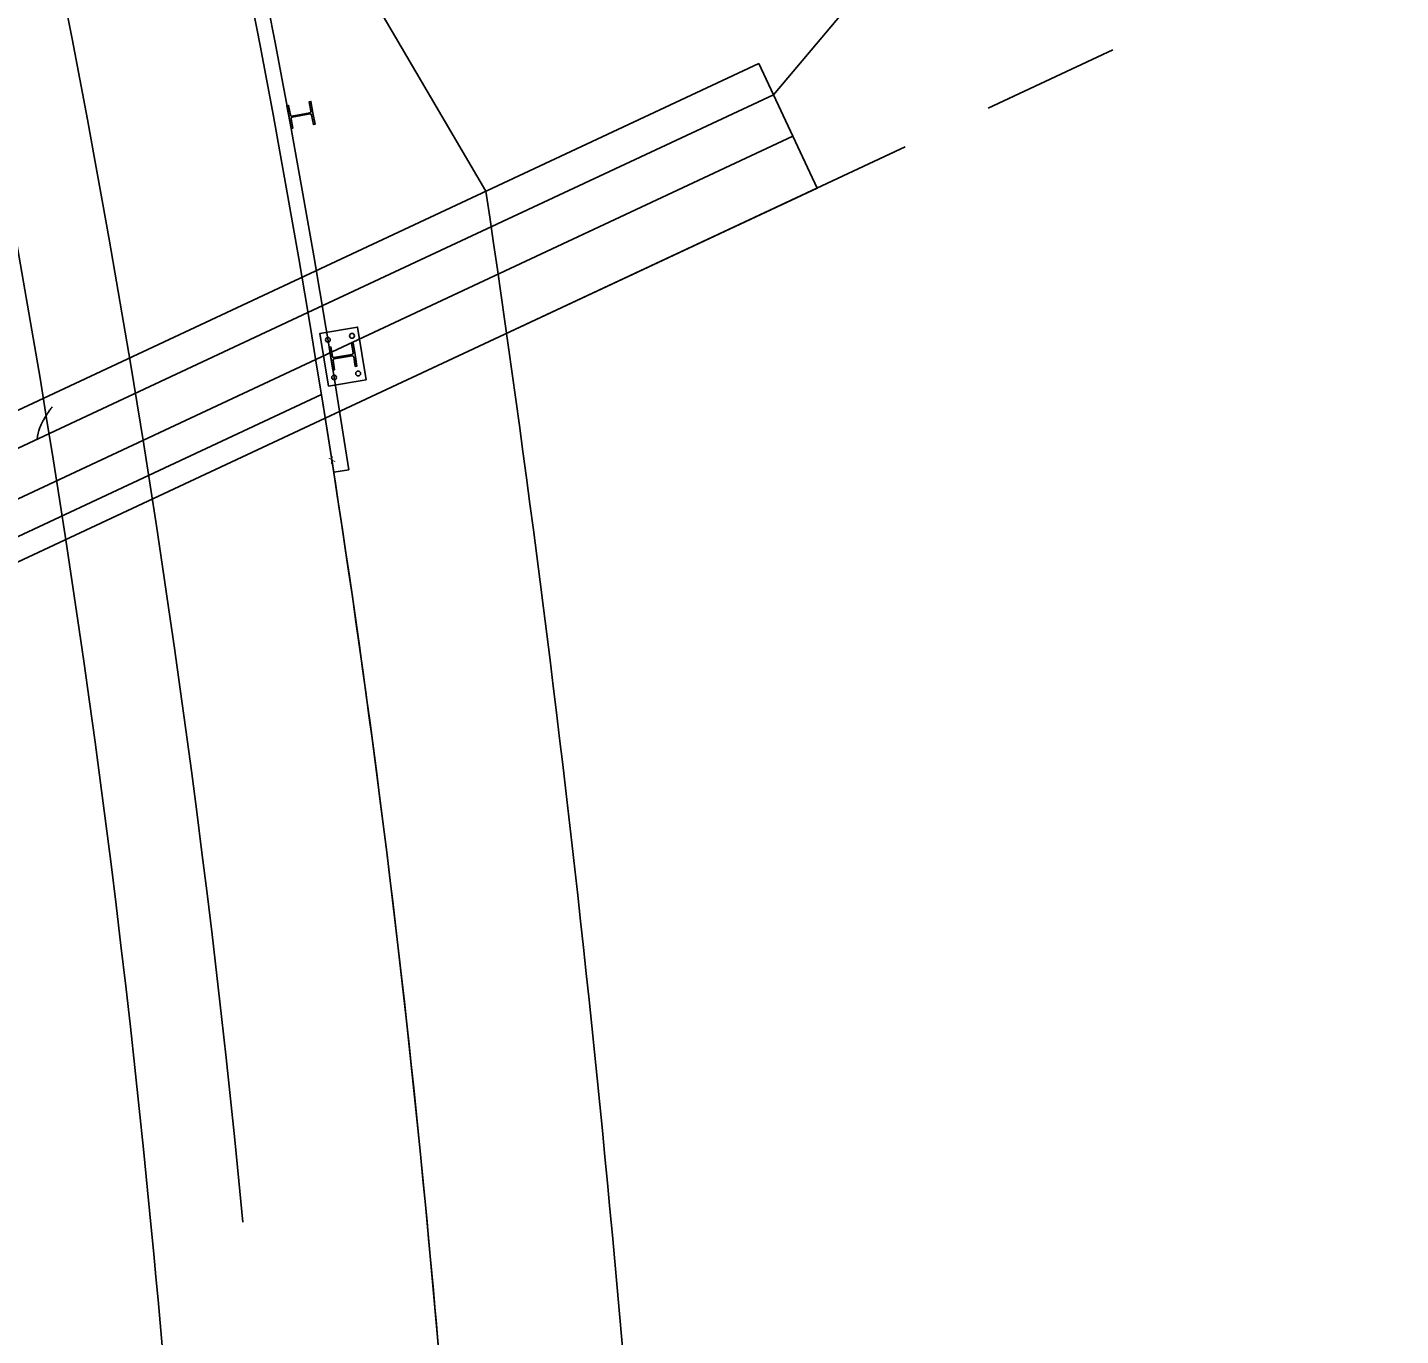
# Model space of a CAD drawing. Extents: x 2355002 to 2355569, y 708374 to 709566.
# Drawn here: x 2355370.84 to 2355400.79, y 709251.3 to 709279.85 of the extents above; entities that cross this region are included whole.
import ezdxf

# ---------------------------------------------------------------- set-up
doc = ezdxf.new("R2010")
doc.units = 0
for name, color, linetype in [('BD_X_Building', 7, 'Continuous'), ('BR_X_Brg_Centerline', 7, 'Continuous'), ('BR_X_Gen_Approach_Slab', 7, 'Continuous'), ('BR_X_Rail_Stl_Det', 7, 'Continuous'), ('DR_X_Cells', 7, 'Continuous'), ('DT_X_Slope_Break_Line', 7, 'Continuous'), ('GK_Drainage_Nodes', 7, 'Continuous'), ('PM_X_Edge_Line', 7, 'Continuous'), ('PM_X_Stop_Line', 7, 'Continuous'), ('PV_X_Driveway', 7, 'Continuous'), ('RD_X_GR_Lt', 7, 'Continuous'), ('VG_X_Cells', 7, 'Continuous'), ('VG_X_Tree_Line_Rt', 7, 'Continuous')]:
    doc.layers.add(name, color=color, linetype=linetype)

msp = doc.modelspace()

# ---------------------------------------------------------------- linework, layer by layer
at = {"layer": 'BD_X_Building'}
msp.add_arc((2355104.75, 709227.886), 272.024, 5.4603, 29.69206, dxfattribs=at)
at = {"layer": 'BR_X_Brg_Centerline'}
msp.add_line((2355335.913, 709253.31), (2355387.539, 709277.472), dxfattribs=at)
at = {"layer": 'BR_X_Gen_Approach_Slab'}
msp.add_line((2355343.137, 709255.863), (2355377.253, 709271.831), dxfattribs=at)
for centre, radius, start, end in [((2355104.75, 709227.886), 276.024, 5.45948, 9.16072), ((2354973.054, 709215.293), 408.32, 3.78138, 5.4603)]:
    msp.add_arc(centre, radius, start, end, dxfattribs=at)
at = {"layer": 'BR_X_Rail_Stl_Det'}
msp.add_line((2355377.85, 709270.19), (2355377.521, 709270.139), dxfattribs=at)
for points in [[(2355376.591, 709277.851), (2355376.629, 709277.644), (2355376.592, 709277.638), (2355376.5, 709278.136), (2355376.537, 709278.143), (2355376.575, 709277.936)], [(2355377.024, 709278.018), (2355376.986, 709278.225), (2355377.023, 709278.232), (2355377.069, 709277.983)], [(2355376.61, 709277.912), (2355377, 709277.984)], [(2355377.005, 709277.958), (2355376.615, 709277.886)], [(2355377.069, 709277.983), (2355377.115, 709277.734), (2355377.077, 709277.727), (2355377.039, 709277.934)], [(2355378.231, 709272.153), (2355378.042, 709273.304), (2355377.219, 709273.169), (2355377.408, 709272.018), (2355378.231, 709272.153)], [(2355377.507, 709272.581), (2355377.541, 709272.374), (2355377.504, 709272.368), (2355377.422, 709272.868), (2355377.459, 709272.874), (2355377.493, 709272.667)], [(2355377.943, 709272.74), (2355377.909, 709272.948), (2355377.946, 709272.954), (2355377.987, 709272.704)], [(2355377.527, 709272.642), (2355377.918, 709272.706)], [(2355377.923, 709272.68), (2355377.532, 709272.616)], [(2355377.987, 709272.704), (2355378.028, 709272.454), (2355377.991, 709272.448), (2355377.957, 709272.655)]]:
    msp.add_lwpolyline(points, dxfattribs=at)
for centre in [(2355377.395, 709273.029), (2355377.92, 709273.115), (2355377.53, 709272.207), (2355378.055, 709272.293)]:
    msp.add_circle(centre, 0.0521, dxfattribs=at)
for centre, radius, start, end in [((2355104.75, 709227.887), 276.357, 8.80517, 29.69195), ((2355104.75, 709227.887), 276.024, 8.80517, 29.69195), ((2355104.75, 709227.887), 276.024, 8.80517, 29.69195), ((2355376.605, 709277.941), 0.0298, 190.4236, 280.4236), ((2355376.62, 709277.857), 0.0298, 100.4236, 190.4236), ((2355376.994, 709278.013), 0.0298, 280.4236, 10.4236), ((2355377.01, 709277.928), 0.0298, 10.4236, 100.4236), ((2355377.522, 709272.671), 0.0298, 189.3148, 279.3148), ((2355377.536, 709272.586), 0.0298, 99.3148, 189.3148), ((2355377.913, 709272.736), 0.0298, 279.3148, 9.3148), ((2355377.927, 709272.65), 0.0298, 9.3148, 99.3148)]:
    msp.add_arc(centre, radius, start, end, dxfattribs=at)
at = {"layer": 'DR_X_Cells'}
for p, q in [((2355376.958, 709273.624), (2355387.115, 709278.378)), ((2355387.115, 709278.378), (2355388.069, 709276.34)), ((2355377.336, 709271.317), (2355388.069, 709276.34))]:
    msp.add_line(p, q, dxfattribs=at)
at = {"layer": 'DT_X_Slope_Break_Line'}
for p, q in [((2355394.515, 709279.357), (2355391.798, 709278.086)), ((2355379.219, 709272.199), (2355389.986, 709277.238))]:
    msp.add_line(p, q, dxfattribs=at)
at = {"layer": 'GK_Drainage_Nodes'}
for p in [(2355335.171, 709254.895), (2355387.115, 709278.378)]:
    msp.add_line(p, (2355386.797, 709279.057), dxfattribs=at)
at = {"layer": 'PM_X_Edge_Line'}
for centre, radius, start, end in [((2355104.75, 709227.886), 270.024, 5.4603, 29.69206), ((2354973.053, 709215.301), 402.321, 0.87055, 5.45927)]:
    msp.add_arc(centre, radius, start, end, dxfattribs=at)
at = {"layer": 'PM_X_Stop_Line'}
msp.add_lwpolyline([(2355335.489, 709254.216), (2355321.375, 709256.458), (2355319.8, 709266.418), (2355329.767, 709266.443), (2355381.288, 709290.828), (2355396.694, 709299.84), (2355400.793, 709294.613), (2355387.115, 709278.378)], dxfattribs=at)
msp.add_spline([(2355371.05, 709270.859), (2355371.111, 709271.112), (2355371.238, 709271.358), (2355371.273, 709271.412), (2355371.307, 709271.464), (2355371.343, 709271.515), (2355371.378, 709271.564)], degree=3, dxfattribs=at)
at = {"layer": 'PV_X_Driveway'}
msp.add_arc((2354973.054, 709215.293), 408.321, 5.4603, 5.46089, dxfattribs=at)
at = {"layer": 'RD_X_GR_Lt'}
for centre, radius, start, end in [((2355104.75, 709227.886), 276.024, 5.4603, 8.8609), ((2354973.054, 709215.293), 408.321, 354.60465, 5.46089)]:
    msp.add_arc(centre, radius, start, end, dxfattribs=at)
at = {"layer": 'VG_X_Cells'}
for p, q in [((2355342.916, 709257.692), (2355376.958, 709273.624)), ((2355343.198, 709255.34), (2355377.336, 709271.317))]:
    msp.add_line(p, q, dxfattribs=at)
at = {"layer": 'VG_X_Tree_Line_Rt'}
msp.add_line((2355374.259, 709287.501), (2355380.841, 709276.27), dxfattribs=at)
msp.add_arc((2354973.054, 709215.293), 412.32, 3.401, 8.50442, dxfattribs=at)

# ---------------------------------------------------------------- texts
at = {"layer": 'BD_X_Building'}
msp.add_text('X', height=0.14, rotation=25.0808, dxfattribs=at).set_placement((2355377.454, 709270.315))

doc.saveas('drawing.dxf')
